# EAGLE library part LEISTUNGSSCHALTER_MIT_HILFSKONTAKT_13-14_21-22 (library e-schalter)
Leistungsschalter mit Hilfskontakten 13, 14, 21, 22
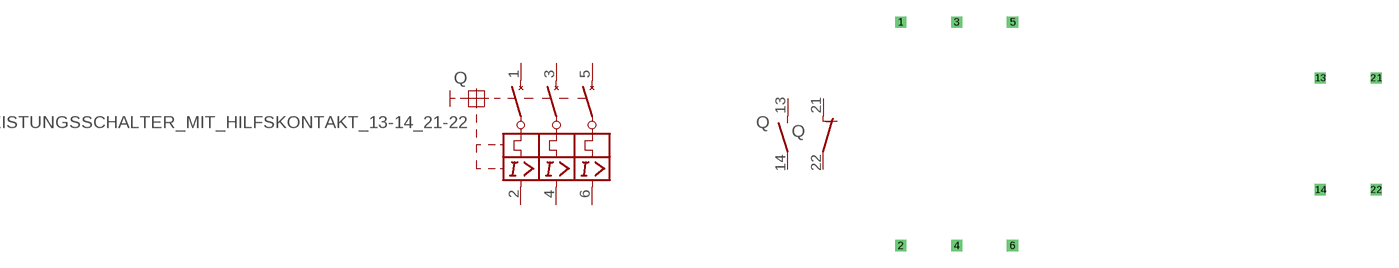
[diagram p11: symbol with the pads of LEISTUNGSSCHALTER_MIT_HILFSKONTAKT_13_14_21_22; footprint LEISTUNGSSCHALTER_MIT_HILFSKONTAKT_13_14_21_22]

Designator prefix Q; gates G$1=LEISTUNGSSCHALTER_MIT_HILFSKONTAKT_13_14_21_22 G$2=SCHLIESSER G$3=OEFFNER

## LEISTUNGSSCHALTER_MIT_HILFSKONTAKT_13-14_21-22  [LEISTUNGSSCHALTER_MIT_HILFSKONTAKT_13_14_21_22]
1  G$1:1  pas
2  G$1:2  pas
3  G$1:3  pas
4  G$1:4  pas
5  G$1:5  pas
6  G$1:6  pas
13  G$2:13  pas
14  G$2:14  pas
21  G$3:21  pas
22  G$3:22  pas

## Footprint LEISTUNGSSCHALTER_MIT_HILFSKONTAKT_13_14_21_22 (pad centres in mm)
Dummy
drill 0.5 pad 1 square: 1 -5.08,7.62; 2 -5.08,-12.7; 3 0,7.62; 4 0,-12.7; 5 5.08,7.62; 6 5.08,-12.7; 13 33.02,2.54; 14 33.02,-7.62; 21 38.1,2.54; 22 38.1,-7.62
